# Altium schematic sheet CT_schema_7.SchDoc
size 371 x 336 mm
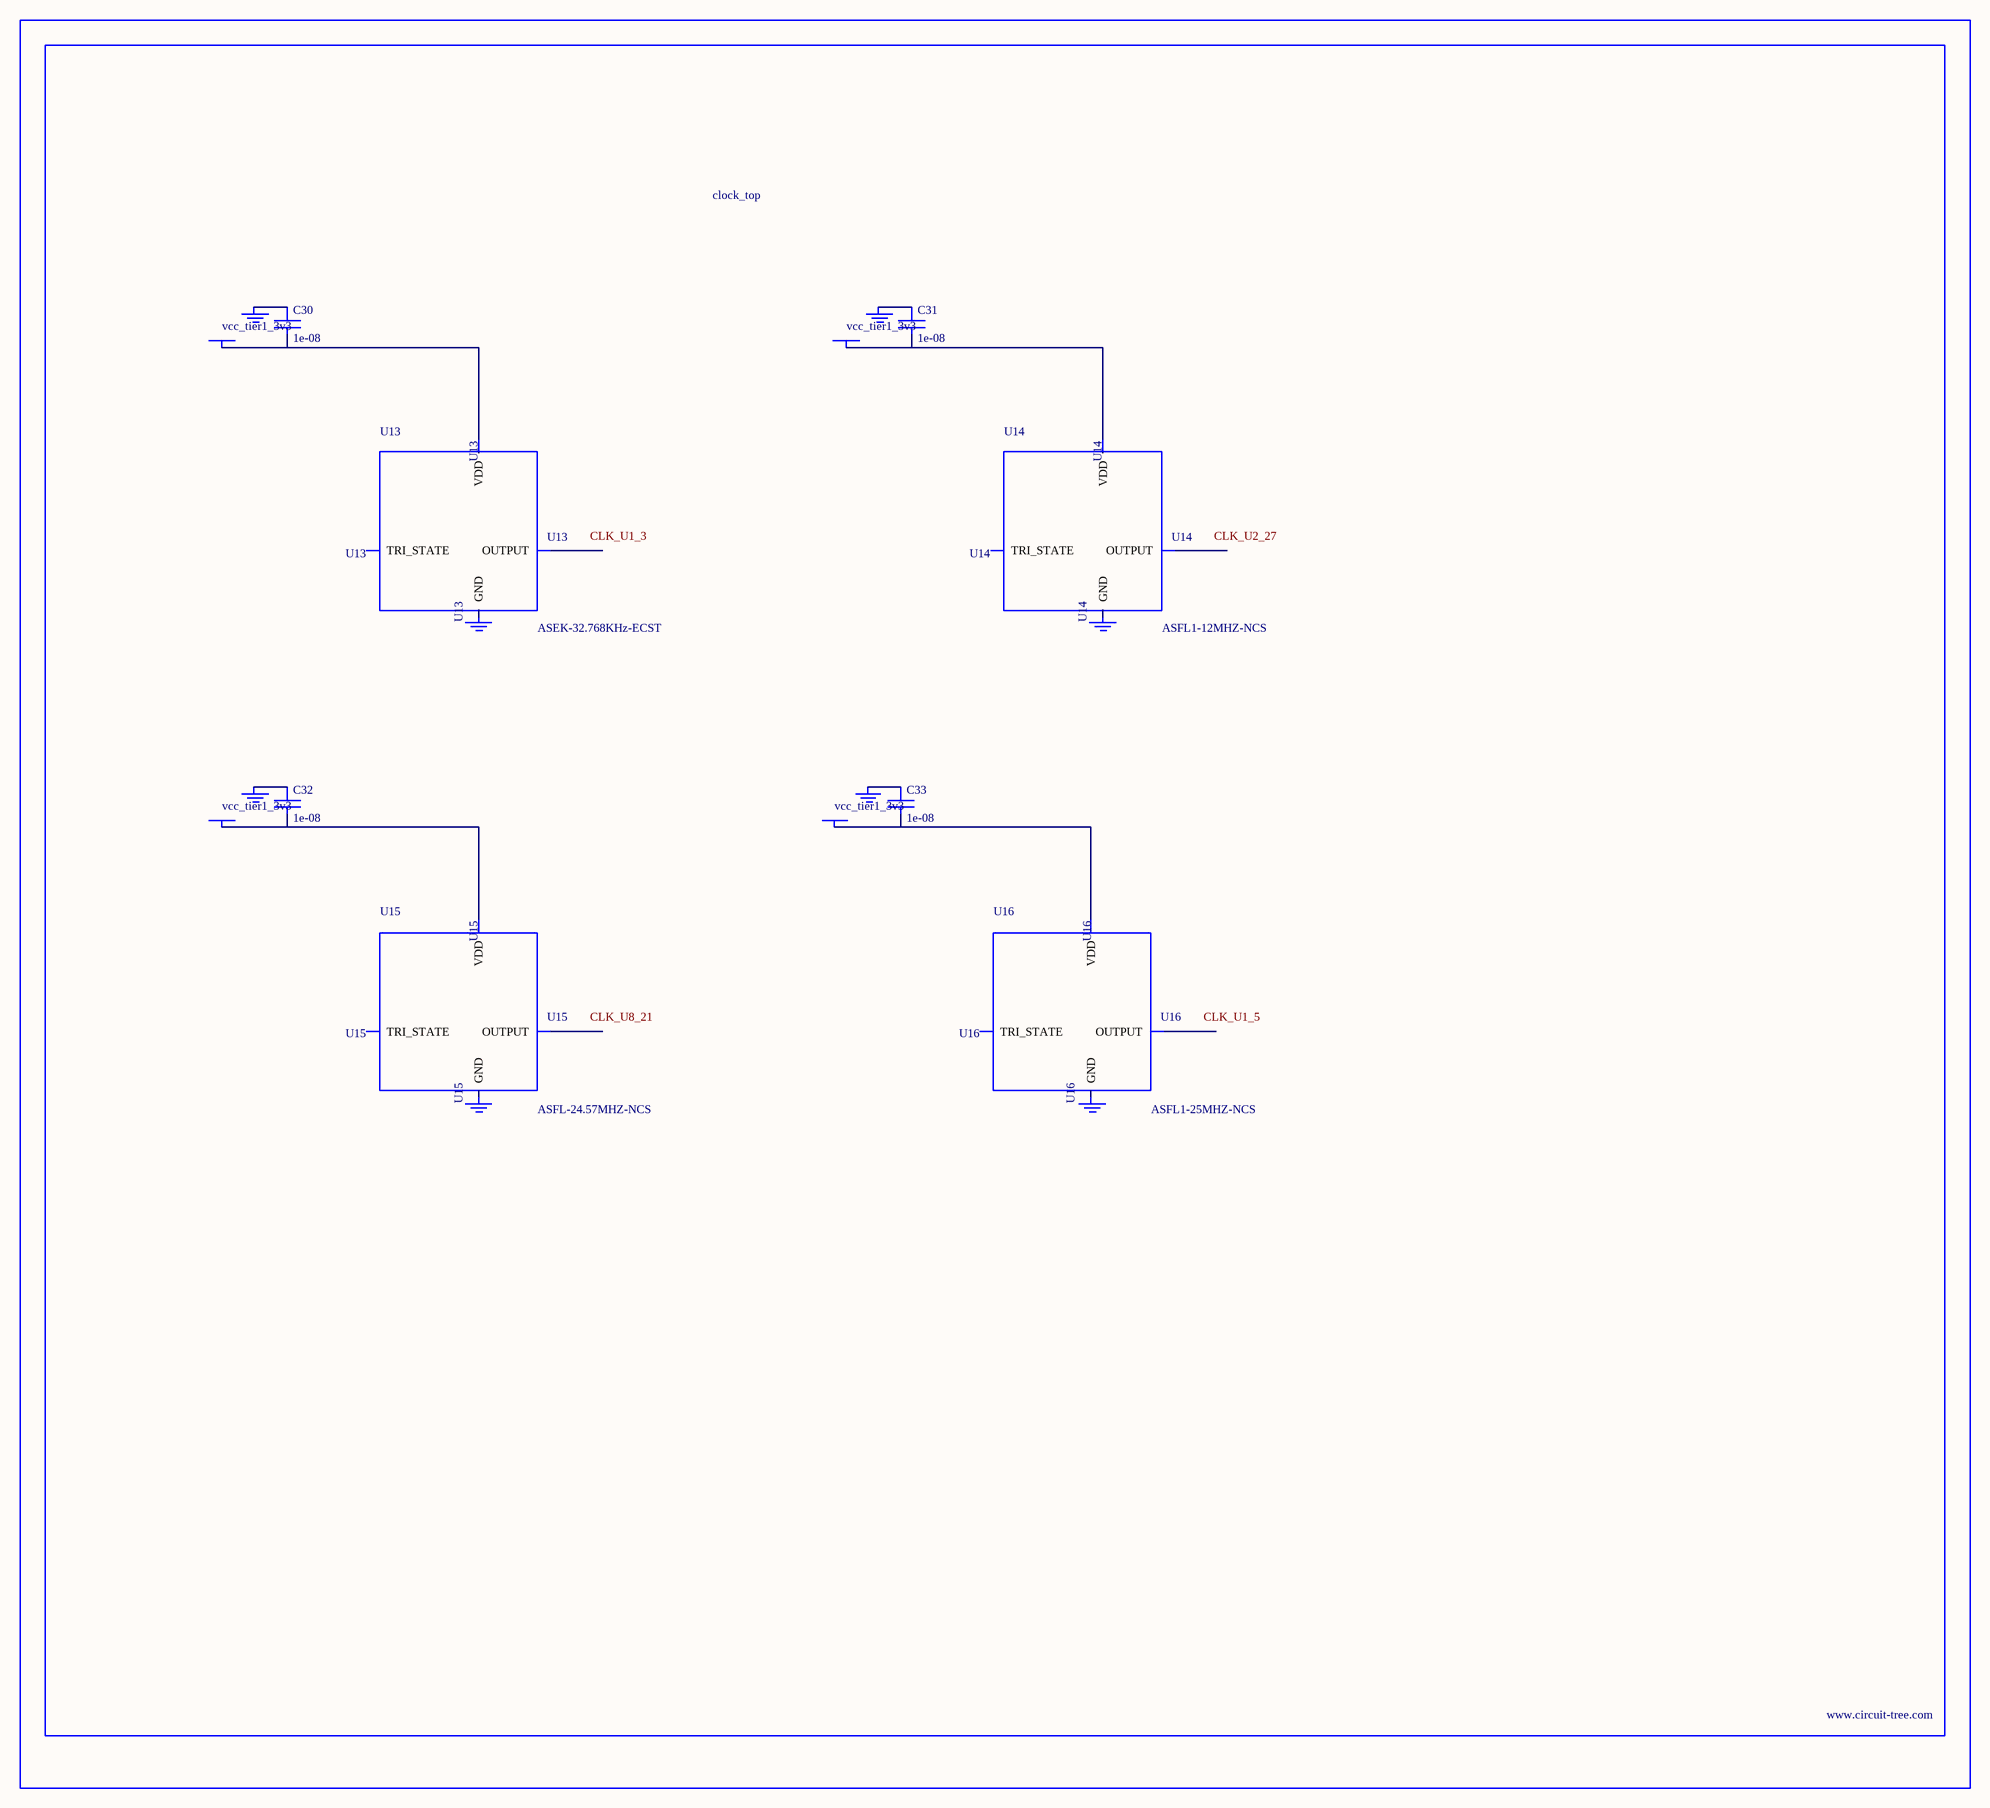
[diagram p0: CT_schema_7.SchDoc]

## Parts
BORDER6  (no value)
C30  1e-08  [C0402]
C31  1e-08  [C0402]
C32  1e-08  [C0402]
C33  1e-08  [C0402]
GND_INSTANCE_6_0  (no value)
GND_INSTANCE_6_1  (no value)
GND_INSTANCE_6_2  (no value)
GND_INSTANCE_6_3  (no value)
GND_INSTANCE_6_4  (no value)
GND_INSTANCE_6_5  (no value)
GND_INSTANCE_6_6  (no value)
GND_INSTANCE_6_7  (no value)
POWER_INSTANCE_6_0  vcc_tier1_3v3
POWER_INSTANCE_6_1  vcc_tier1_3v3
POWER_INSTANCE_6_2  vcc_tier1_3v3
POWER_INSTANCE_6_3  vcc_tier1_3v3
U13  ASEK-32.768KHz-ECST  [ASEK]
U14  ASFL1-12MHZ-NCS  [ASFL1]
U15  ASFL-24.57MHZ-NCS  [ASFL1]
U16  ASFL1-25MHZ-NCS  [ASFL1]

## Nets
NetC30_1: C30.1 GND_INSTANCE_6_0.0(GND)
NetC30_2: C30.2 POWER_INSTANCE_6_0.0(PWR) U13.4(VDD)
NetC31_1: C31.1 GND_INSTANCE_6_2.0(GND)
NetC31_2: C31.2 POWER_INSTANCE_6_1.0(PWR) U14.4(VDD)
NetC32_1: C32.1 GND_INSTANCE_6_4.0(GND)
NetC32_2: C32.2 POWER_INSTANCE_6_2.0(PWR) U15.4(VDD)
NetC33_1: C33.1 GND_INSTANCE_6_6.0(GND)
NetC33_2: C33.2 POWER_INSTANCE_6_3.0(PWR) U16.4(VDD)

Not connected (* = marked no-connect by the designer): GND_INSTANCE_6_1 0(GND); GND_INSTANCE_6_3 0(GND); GND_INSTANCE_6_5 0(GND); GND_INSTANCE_6_7 0(GND); U13 1(TRI_STATE) 2(GND) 3(OUTPUT); U14 1(TRI_STATE) 2(GND) 3(OUTPUT); U15 1(TRI_STATE) 2(GND) 3(OUTPUT); U16 1(TRI_STATE) 2(GND) 3(OUTPUT)

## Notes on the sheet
- Labels drawn without touching a wire or pin: CLK_U1_3, CLK_U1_5, CLK_U2_27, CLK_U8_21

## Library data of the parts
BORDER6 = BORDER_PAGE6
C30-C33 = C0402C103K3RAC
GND_INSTANCE_6_0-GND_INSTANCE_6_7 = GND
POWER_INSTANCE_6_0-POWER_INSTANCE_6_3 = PWR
